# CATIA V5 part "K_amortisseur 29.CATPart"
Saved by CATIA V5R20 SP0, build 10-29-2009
Part number: amortisseur 29
Publications: "longueur amortisseur", "demi largeur balancier", "epaisseur pieces", "demi largeur tige", "Plan.-55", "liaison 28/29 sur 29", "Droite.1"
Bounding box of the stored display mesh (mm): x -80 to 30, y 260.001 to 673.491, z 105.372 to 309.987
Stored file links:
  G:\Khaled_CFAO_2011\SIL\SIL_GR2\mdardier\Khaled\CAD_ThinkMOTION\K_amortisseur 29.CATPart
  G:\Khaled_CFAO_2011\SIL\SIL_GR2\mdardier\Khaled\CAD_ThinkMOTION\K_ass_tandem.CATProduct
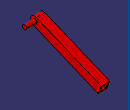
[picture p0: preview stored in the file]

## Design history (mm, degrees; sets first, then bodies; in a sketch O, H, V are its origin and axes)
External parameters (linked from other documents)
  `External.longueur amortisseur` = 410 mm
  `External.demi largeur balancier` = 50 mm
  `External.epaisseur pieces` = 30 mm
  `External.demi largeur tige` = 17.5 mm
Set1
  Plane1 "Plan.-55": linked copy from another document
  Point1 "liaison 28/29 sur 29": linked copy from another document
  Line1: linked copy from another document
Body1 (main body)
  Sketch1 on Plane1, origin (-55, 0, 0), H (0, 1, 0), V (0, 0, 1)
    construction line L1 (285, 285) -> (663.9472, 128.4783)
    point P1 (285, 285)
    line L2 (294.544, 308.1065) -> (673.4912, 151.5849)
    line L3 (654.4032, 105.3718) -> (275.456, 261.8935)
    arc A1 centre (285, 285) radius 25 from (275.456, 261.8935) to (294.544, 308.1065) cw
    reference projected point E1 (285, 285) from Point1
    reference projected line E2 (285, 285) -> (663.9472, 128.4783) from Line1
    line L4 (673.4912, 151.5849) -> (654.4032, 105.3718)
    distance L1 L2 = 25 {= `External.demi largeur balancier` /2}
    length L2 = 410 {= `External.longueur amortisseur`}
    tangency: A1 L2, A1 L3
    coincidence: P1 E1
    parallelism: L1 E2
    perpendicularity: L4 L1, L3 L4
  Pad1: profile Sketch1, direction (1, 0, 0), length 25 {= `External.demi largeur balancier` /2}, mirrored extent
  Sketch2 on end face of Pad1, origin (-30, 0, 0), H (0, 1, 0), V (0, 0, 1)
    circle A1 centre (285, 285) radius 12.5
    point P1 (285, 285)
    reference projected point E1 (285, 285) from Point1
    radius A1 = 12.5 {= `External.demi largeur balancier` /4}
    coincidence: P1 E1
  Pad2: profile Sketch2, direction (1, 0, 0), length 60 {= `External.epaisseur pieces` *2}
  Sketch3 on face of Pad1 from Sketch1.L4, origin (0, 521.8499, -215.5467), H (-1, 0, 0), V (0, 0.3818, 0.9243)
    line L1 (36.5, 390.7162) -> (73.5, 390.7162)
    line L2 (73.5, 390.7162) -> (73.5, 353.7162)
    line L3 (73.5, 353.7162) -> (36.5, 353.7162)
    line L4 (36.5, 353.7162) -> (36.5, 390.7162)
    reference projected line E1 (80, 397.2162) -> (30, 397.2162) from edge [face of Pad1 from Sketch1.L2 | face of Pad1 from Sketch1.L4]
    reference projected line E2 (30, 347.2162) -> (30, 397.2162) from edge [face of Pad1 from Sketch1.L4 | end face of Pad1]
    reference projected line E3 (80, 347.2162) -> (30, 347.2162) from edge [face of Pad1 from Sketch1.L4 | face of Pad1 from Sketch1.L3]
    reference projected line E4 (80, 347.2162) -> (80, 397.2162) from edge [start face of Pad1 | face of Pad1 from Sketch1.L4]
    distance L1 E1 = 6.5 {= `External.demi largeur balancier` /2-`External.demi largeur tige` -0.001}
    distance L4 E2 = 6.5 {= `External.demi largeur balancier` /2-`External.demi largeur tige` -0.001}
    distance L3 E3 = 6.5 {= `External.demi largeur balancier` /2-`External.demi largeur tige` -0.001}
    distance L2 E4 = 6.5 {= `External.demi largeur balancier` /2-`External.demi largeur tige` -0.001}
    horizontal: L1 H, L3 H
    vertical: L2 V, L4 V
  Pocket1: profile Sketch3, direction (0, -0.9243, 0.3818), length 360 {= `External.longueur amortisseur` -`External.demi largeur balancier`}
